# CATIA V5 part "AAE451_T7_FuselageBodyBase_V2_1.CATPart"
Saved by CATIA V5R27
Part number: FB1
Bounding box of the stored display mesh (mm): x -98.443 to 98.443, y -250 to -100, z -67 to 0
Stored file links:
  U:\Personal\Downloads\AAE451_T7_FuselageAssemble_V2 (2)\AAE451_T7_FuselageAssemble_V2\AAE451_T7_FuselageBodyBase_V2_1.CATPart
  W:\AAE 451\AAE451_T7_FuselageBody.CATPart
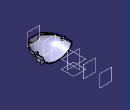
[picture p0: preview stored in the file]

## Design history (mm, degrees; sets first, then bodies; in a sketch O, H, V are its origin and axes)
Body1 (main body)
Body2
  Plane1: type Offset, RefPlane zx-plane, Offset 250, reversed
  Plane2: type Offset, RefPlane zx-plane, Offset 100
  Sketch1 on Plane1, origin (0, -250, 0), H (-1, 0, 0), V (0, 0, 1)
    circle A1 centre (0, 0) radius 35
    distance O A1 = 35
  Plane3: type Offset, RefPlane zx-plane, Offset 150, reversed
  Sketch2 on Plane2, origin (0, 100, 0), H (-1, 0, 0), V (0, 0, 1)
    construction line L1 (0, 60) -> (0, -40)
    point P1 (0, 60)
    construction line L2 (-92.2886, 30) -> (87.7114, 30)
    point P5 (0, 30)
    coincidence: P1 V, P5 L2, P5 L1
    vertical: L1 V
    horizontal: L2 H
  Sketch3 on Plane2, origin (0, 100, 0), H (-1, 0, 0), V (0, 0, 1)
    construction line L1 (0, -100) -> (0, 70)
    point P1 (0, -100)
    construction line L2 (-103.4986, 30) -> (116.5014, 30)
    point P5 (0, 30)
    point P6 (0, 60)
    construction line L3 (-60, 60) -> (60, 60)
    point P7 (-60, 60)
    reference projected curve E1 from Sketch4.E1
    ellipse A1 centre (0, 60) semi-axes 60, 35 rotation 180 from (-60, 60) to (60, 60)
    point P8 (-60, 60)
    point P9 (60, 60)
    point P10 (60, 60)
    point P11 (-60, 60)
    ellipse A2 centre (0, 60) semi-axes 60, 35 rotation 180 from (-60, 60) to (60, 60)
    "Radius" A1 = 60
    "Radius" A1 = 35
    coincidence: P1 V, P5 L2, P5 L1, P6 L1, A1 P7, P7 L3, P6 L3
    vertical: L1 V
    horizontal: L2 H, L3 H, A1 H
    tangency: L3 E1
    symmetry: P9 P10 L3, P8 P11 L3, A1 A2 L3
  Sketch4 on zx-plane, origin (0, 0, 0), H (-1, 0, 0), V (0, 0, 1)
    projected curve E1 from Sketch5.A1
  Sketch5 on Plane3, origin (0, -150, 0), H (-1, 0, 0), V (0, 0, 1)
    construction line L1 (50, 50) -> (50, -50)
    construction line L2 (50, -50) -> (-50, -50)
    construction line L3 (-50, -50) -> (-50, 50)
    construction line L4 (-50, 50) -> (50, 50)
    point P1 (50, 50)
    point P2 (50, -50)
    point P3 (-50, -50)
    point P4 (-50, 50)
    construction line L5 (0, -60) -> (0, 90)
    point P5 (0, -60)
    construction line L6 (-100, 0) -> (110, 0)
    point P7 (-100, 0)
    ellipse A1 centre (0, 0) semi-axes 90.4534, 60 rotation 0
    point P9 (0, 60)
    length L1 = 100
    length L4 = 100
    vertical: L1 V, L3 V, L5 V
    horizontal: L2 H, L4 H, L6 H, A1 H
    equidistance: L1 L3 O, L2 L4 O
    coincidence: P5 V, P7 H, P9 L5, A1 P9, P2 A1, A1 P3, P1 A1, P4 A1
    parallelism: A1 L6
  Loft1: solid, Sections (Sketch3; Sketch4; Sketch5; Sketch1)
  Sketch6 on face of Loft1, origin (0, 100, 0), H (-1, 0, 0), V (0, 0, 1)
    line L1 (-70, 95) -> (70, 95)
    line L2 (70, 95) -> (70, 60)
    line L3 (70, 60) -> (-70, 60)
    line L4 (-70, 60) -> (-70, 95)
    reference projected curve E1 from edge [face of Loft1 | face of Loft1]
    construction line L5 (-60, 60) -> (60, 60)
    length L1 = 140
    horizontal: L1 H, L3 H, L5 H
    vertical: L2 V, L4 V
    coincidence: L3 L5
    tangency: L1 E1
    symmetry: L4 L2 V
  Pocket1: profile Sketch6, direction (0, -1, 0), through (limit type 6)
  Plane4: type Offset, RefPlane Plane2, Offset 100
  Sketch7 on Plane4, origin (0, 200, 0), H (-1, 0, 0), V (0, 0, 1)
    projected line E2 (-60, 60) -> (60, 60) from edge [face of Loft1 | face of Pocket1 from Sketch6.L3]
  Pad1: profile Sketch7, direction (0, 1, 0), up to the existing solid (limit type 3)
  Sketch8 on face of Loft1, origin (0, -250, 0), H (1, 0, 0), V (0, 0, 1)
    line L1 (-97.5192, 0) -> (97.5192, 0)
    point P1 (-97.5192, 0)
    point P2 (97.5192, 0)
    projected line E1 (-62.8781, 60) -> (63.056, 60) from edge [face of Loft1 | face of Pad1]
    line L2 (-97.5192, 0) -> (-62.8781, 60)
    line L3 (97.5192, 0) -> (63.056, 60)
    angle L1 L2 = 60
    horizontal: L1 H
    symmetry: P1 P2 V
    coincidence: H L1
  Pocket2: profile Sketch8, direction (0, 1, 0), through (limit type 3)
  Shell1: ExtOffset 0, Face face of Pocket2 from Sketch8.L1, IntOffset 4
  Sketch9 on face of Pocket2 from Sketch8.L1, origin (0, 0, 0), H (1, 0, 0), V (0, 1, 0)
    arc A1 centre (93.4432, -150) radius 5 from (93.4432, -155) to (93.4432, -145) ccw
    point P1 (93.4432, -150)
    line L1 (93.4432, -145) -> (86.4534, -145)
    point P2 (86.4534, -145)
    line L2 (93.4432, -155) -> (86.433, -155)
    point P3 (86.433, -155)
    reference projected curve E1 from edge [face of Pocket2 from Sketch8.L1 | face of Shell1]
    reference projected curve E2 from edge [face of Shell1 | face of Pocket2 from Sketch8.L1]
    reference intersected line E3 through (0, -150) direction (-1, 0) from Plane3
    line L3 (86.4534, -145) -> (86.433, -155)
    distance L1 L2 = 10
    distance L3 P1 = 7
    horizontal: L1 H, L2 H
    tangency: L1 A1, L2 A1
    coincidence: P3 E1, P2 E2, E3 P1
  Pad2: profile Sketch9, direction (0, 0, -1), length 10
  RectPattern1: of Pad2, direction 1 instances 3, spacing 75, along yz-plane
  Mirror1: of RectPattern1, about yz-plane
  Plane5: type Offset, RefPlane xy-plane, Offset 55, reversed
  Sketch10 on Plane5, origin (0, 0, -55), H (1, 0, 0), V (0, 1, 0)
    line L1 (67.5, -137.75) -> (-67.5, -137.75)
    line L2 (-67.5, -137.75) -> (-67.5, -162.25)
    line L3 (-67.5, -162.25) -> (67.5, -162.25)
    line L4 (67.5, -162.25) -> (67.5, -137.75)
    construction line L5 (132.2933, -150) -> (-145.9619, -150)
    distance L4 L2 = 135
    length L2 = 24.5
    distance L5 H = 150
    horizontal: L1 H, L3 H
    vertical: L2 V, L4 V
    symmetry: L4 L2 V, L1 L3 L5
  Pad3: profile Sketch10, direction (0, 0, -1), length 12, opposite side up to the existing solid (limit type 2)
  Fillet1: radius 10, on edge [end face of Pad3 | face of Pad3 from Sketch10.L4]; edge [end face of Pad3 | face of Pad3 from Sketch10.L2]
  Sketch11 on face of RectPattern1, origin (0, 0, 0), H (1, 0, 0), V (0, 1, 0)
    circle A1 centre (93.4432, -150) radius 2.5
    reference projected arc E1 centre (93.4432, -150) radius 5 from (93.4432, -155) to (93.4432, -145) ccw from edge [face of Pad2 from Sketch9.A1 | face of RectPattern1]
    radius A1 = 2.5
    concentricity: A1 E1
  Pocket3: profile Sketch11, direction (0, 0, -1), through (limit type 3)
  RectPattern2: of Pocket3, direction 1 instances 3, spacing 75, along yz-plane
  Mirror2: of RectPattern2, about yz-plane
  Plane6 "PRINT CAPACITY": type Offset, RefPlane Plane1, Offset 150
  Sketch12 on Plane6, origin (0, -100, 0), H (-1, 0, 0), V (0, 0, 1)
    point P1 (-2.7383, -33.5)
    line L1 (146.5133, 0) -> (146.5133, -67)
    line L2 (146.5133, -67) -> (-151.9899, -67)
    line L3 (-151.9899, -67) -> (-151.9899, 0)
    line L4 (-151.9899, 0) -> (146.5133, 0)
    reference projected line E1 (-67.5, -67) -> (67.5, -67) from edge [end face of Pad3 | face of Pad3 from Sketch10.L1]
    vertical: L1 V, L3 V
    horizontal: L2 H, L4 H
    equidistance: L1 L3 P1, L2 L4 P1
    coincidence: L4 H, L2 E1
  Pocket4: profile Sketch12, direction (0, 1, 0), through (limit type 3)
  Sketch13 on end face of Pad3, origin (0, 0, -67), H (1, 0, 0), V (0, -1, 0)
    circle A1 centre (-37, 150) radius 2.972
    point P1 (-37, 150)
    reference projected line E1 (-67.5, 162.25) -> (67.5, 162.25) from edge [end face of Pad3 | face of Pad3 from Sketch10.L3]
    reference projected line E2 (67.5, 137.75) -> (-67.5, 137.75) from edge [end face of Pad3 | face of Pad3 from Sketch10.L1]
    circle A2 centre (37, 150) radius 2.972
    radius A1 = 2.972
    distance P1 V = 37
    equidistance: E1 E2 P1
    symmetry: A1 A2 V
  Pocket5: profile Sketch13, direction (0, 0, 1), length 7.79
  Sketch14 on face of RectPattern1, origin (0, 0, 0), H (1, 0, 0), V (0, 1, 0)
    arc A1 centre (-76.4432, -150) radius 5 from (-76.4432, -155) to (-76.4432, -145) ccw
    point P1 (-76.4432, -150)
    line L1 (-86.4534, -145) -> (-76.4432, -145)
    point P2 (-86.4534, -145)
    line L2 (-86.433, -155) -> (-76.4432, -155)
    point P3 (-86.433, -155)
    reference projected line E1 (-86.4534, -145) -> (-86.433, -155) from edge [face of RectPattern1 | face of Mirror1]
    reference projected line E2 (-86.4534, -145) -> (-86.433, -155) from edge [face of RectPattern1 | face of Mirror1]
    line L3 (-86.433, -155) -> (-86.4534, -145)
    construction line L4 (-93.4432, -150) -> (-76.4432, -150)
    point P4 (-93.4432, -150)
    reference projected circle E3 centre (-93.4432, -150) radius 2.5 from edge [face of Mirror2 | face of RectPattern1]
    radius A1 = 5
    distance P1 L3 = 10
    horizontal: L1 H, L2 H, L4 H
    coincidence: P3 E1, P2 E2
    concentricity: P4 E3
    tangency: L1 A1, L2 A1
  Pad4: profile Sketch14, direction (0, 0, -1), length 10
  Sketch15 on face of Pad4, origin (-76.5818, -149.4637, 0), H (1, 0, 0), V (0, 1, 0)
    point P1 (0.1386, -0.5363)
    reference projected arc E1 centre (0.1386, -0.5363) radius 5 from (0.1386, -5.5363) to (0.1386, 4.4637) ccw from edge [face of Pad4 from Sketch14.A1 | start face of Pad4]
    concentricity: P1 E1
  Hole1: placed by Sketch15, at (-76.4432, -150, 0) direction (0, 0, -1), diameter 5.944, depth 8.9, V-bottom angle 120, countersink depth 7.9, countersink angle 8
  Mirror3: of Pad4, Hole1, about yz-plane
  Sketch16 on face of Loft1, origin (9.8103, -250, -14.0284), H (1, 0, 0), V (0, 0, 1)
    point P1 (9.9397, -5.7216)
    reference intersected line E1 through (-9.8103, 0) direction (0, 1) from yz-plane
    reference intersected line E2 through (0, 14.0284) direction (-1, 0) from xy-plane
    distance E1 P1 = 19.75
    distance E2 P1 = 19.75
  Hole2: placed by Sketch16, at (19.75, -250, -19.75) direction (0, 1, 0), diameter 3.5, through (limit type 6)
  Mirror4: of Hole2, about yz-plane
